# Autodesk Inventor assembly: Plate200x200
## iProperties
Created: 2006-02
Part Number: Plate200x200
Document SubType Name: Assembly
Designer: 40664
Stock Number: Plate200x200
CSToolsMass: 0.4
CSToolsVolume: 395476.0
CSToolsArea: 886.0
Author: 40664
